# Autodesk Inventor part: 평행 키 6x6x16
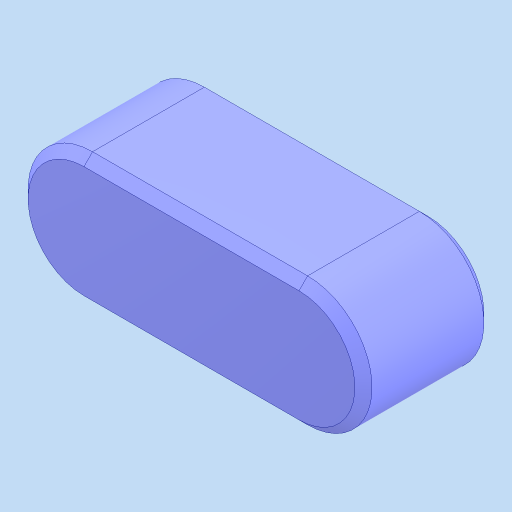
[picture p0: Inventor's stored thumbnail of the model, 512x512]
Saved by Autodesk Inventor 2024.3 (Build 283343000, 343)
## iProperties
Created: 2025-11
Part Number: 평행 키 6x6x16
Material: 강철, 연강
Description: 키 및 해당 키홈
Document SubType Name: Modeling
Designer: PC2-03
Density: 7.85 g/cm^3
Appearance: 기본값
Author: jhkim
Sending System: Autodesk Inventor 2026
Preprocessor: ST-DEVELOPER v20.1
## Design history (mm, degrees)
feature "Solid1"
node "솔리드1"
